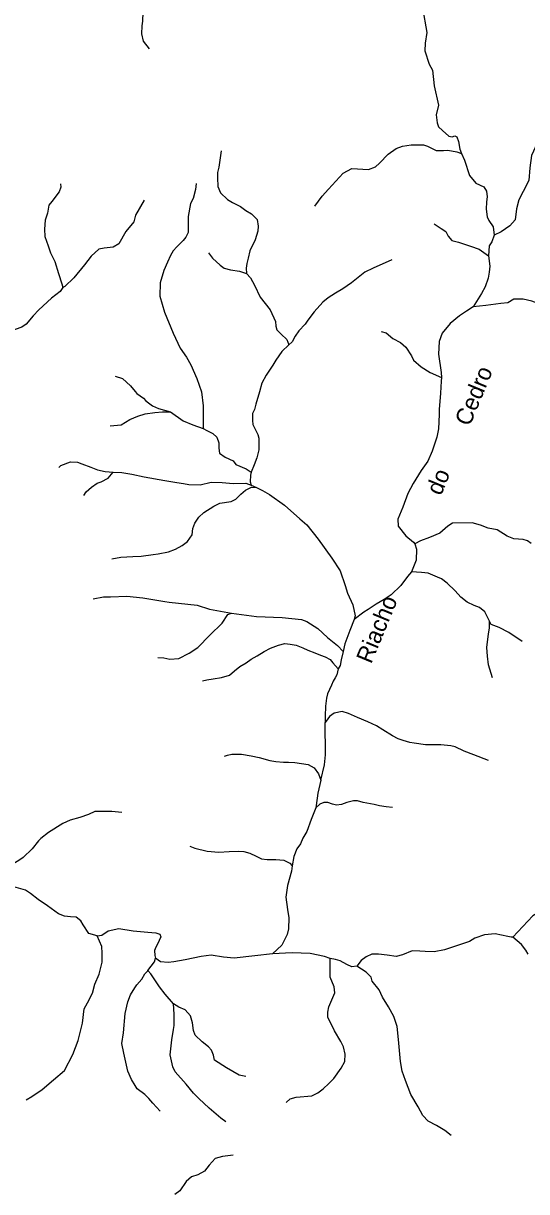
# Model space of a CAD drawing. Extents: x 717.8 to 772.7, y 8672.2 to 8728.
# Drawn here: x 755.19 to 761.18, y 8700.84 to 8714.76 of the extents above; entities that cross this region are included whole.
import ezdxf
from ezdxf.enums import TextEntityAlignment as Align

# ---------------------------------------------------------------- set-up
doc = ezdxf.new("R2010")
doc.units = 0
doc.header["$LTSCALE"] = 0.08
doc.linetypes.add('LONG_DASHED', pattern=[7.5, 6, -1.5])
doc.layers.add('61', color=7, linetype='Continuous')
doc.layers.add('9', color=7, linetype='LONG_DASHED', lineweight=25)

msp = doc.modelspace()

# ---------------------------------------------------------------- linework, layer by layer
at = {"layer": '9'}
for points in [[(759.8819, 8715.4201), (759.893, 8715.3655), (759.8987, 8715.3039), (759.905, 8715.2034), (759.9117, 8715.0996), (759.938, 8714.9401), (759.99, 8714.6467), (759.9703, 8714.5208), (759.967, 8714.4305), (760.0174, 8714.2699), (760.0568, 8714.1993), (760.0794, 8714.0103), (760.1298, 8713.7807), (760.1022, 8713.6647), (760.1121, 8713.5723), (760.1309, 8713.5228), (760.1789, 8713.48), (760.2538, 8713.4108), (760.2908, 8713.4041), (760.3245, 8713.4166), (760.349, 8713.406), (760.3687, 8713.35), (760.3845, 8713.2586), (760.4042, 8713.206)], [(756.688, 8714.4531), (756.6164, 8714.5436), (756.595, 8714.6315), (756.5994, 8714.7258), (756.6082, 8714.7823), (756.6129, 8714.8878), (756.5833, 8714.9933), (756.5507, 8715.1278), (756.5244, 8715.1785)], [(761.3778, 8713.4159), (761.3027, 8713.3282), (761.2362, 8713.1828), (761.2154, 8713.0358), (761.2052, 8712.8849), (761.1372, 8712.7549), (761.0846, 8712.6559), (761.0598, 8712.546), (761.0413, 8712.4176), (760.9787, 8712.3465), (760.875, 8712.273), (760.7924, 8712.2328)], [(757.5414, 8713.2372), (757.5143, 8713.0432), (757.4983, 8712.9809), (757.4958, 8712.9172), (757.5015, 8712.8125), (757.5318, 8712.7367), (757.6156, 8712.6593), (757.6747, 8712.621), (757.772, 8712.5739), (757.8351, 8712.5268), (757.9021, 8712.4877), (757.9684, 8712.4199), (757.9827, 8712.3401), (757.978, 8712.2826), (757.9444, 8712.1773), (757.8831, 8712.0467), (757.8627, 8711.9583), (757.8463, 8711.8964), (757.8399, 8711.8405), (757.8438, 8711.7769)], [(758.6555, 8712.5782), (758.743, 8712.6976), (758.8189, 8712.7828), (758.9939, 8712.9718), (759.0955, 8713.0282), (759.2967, 8713.0175), (759.3795, 8713.0462), (759.4264, 8713.0925), (759.5298, 8713.1965), (759.6273, 8713.2647), (759.7017, 8713.2918), (759.8055, 8713.3089), (759.9511, 8713.3089), (759.9983, 8713.2918), (760.1024, 8713.2426), (760.1886, 8713.2425), (760.2392, 8713.2461), (760.3476, 8713.2267), (760.4042, 8713.206)], [(760.4042, 8713.206), (760.4384, 8713.126), (760.4994, 8712.9429), (760.5735, 8712.8528), (760.6701, 8712.8101), (760.7018, 8712.7582), (760.708, 8712.6891), (760.7011, 8712.6311), (760.697, 8712.5439), (760.7085, 8712.4526), (760.7289, 8712.4099), (760.7787, 8712.3344), (760.7924, 8712.2328)], [(755.6293, 8712.843), (755.6304, 8712.8043), (755.6103, 8712.7509), (755.523, 8712.6363), (755.4882, 8712.5899), (755.472, 8712.4947), (755.4461, 8712.4124), (755.4358, 8712.3029), (755.442, 8712.2192), (755.4808, 8712.1078), (755.508, 8712.0247), (755.5597, 8711.9216), (755.606, 8711.7753), (755.6432, 8711.6542), (755.6552, 8711.6119)], [(757.2436, 8712.8502), (757.2368, 8712.7754), (757.2088, 8712.6701), (757.1765, 8712.6111), (757.1466, 8712.4574), (757.1481, 8712.2653), (757.1209, 8712.211), (757.087, 8712.1701), (757.0122, 8712.0953), (756.9713, 8712.0463), (756.9374, 8711.9905), (756.9034, 8711.9117), (756.8597, 8711.8109), (756.8144, 8711.6637), (756.8128, 8711.5068), (756.8662, 8711.3175), (756.9681, 8711.0659), (757.0532, 8710.8863), (757.1268, 8710.7803), (757.1794, 8710.6881), (757.2505, 8710.5279), (757.3059, 8710.3676), (757.3263, 8710.2022), (757.3282, 8710.0733), (757.3269, 8709.9324)], [(756.6227, 8712.6508), (756.5218, 8712.4708), (756.5007, 8712.3934), (756.4053, 8712.2776), (756.3207, 8712.1299), (756.2534, 8712.0916), (756.1471, 8712.079), (756.086, 8712.0665), (755.9942, 8711.9822), (755.9133, 8711.881), (755.7848, 8711.727), (755.681, 8711.6204), (755.6552, 8711.6119)], [(760.0788, 8712.3685), (760.1615, 8712.3142), (760.2182, 8712.2786), (760.2445, 8712.2201), (760.2879, 8712.1697), (760.3682, 8712.1498), (760.4491, 8712.1221), (760.5115, 8712.102), (760.6131, 8712.0662), (760.7258, 8711.9874)], [(760.7924, 8712.2328), (760.7646, 8712.1554), (760.7315, 8712.1069), (760.7258, 8711.9874)], [(757.3918, 8712.0242), (757.439, 8711.9611), (757.5276, 8711.8748), (757.5763, 8711.842), (757.652, 8711.8223), (757.7584, 8711.8061), (757.8438, 8711.7769)], [(759.5725, 8711.9408), (759.3518, 8711.8398), (759.2515, 8711.7912), (759.1333, 8711.6988), (759.0925, 8711.6649), (758.9919, 8711.5954), (758.9012, 8711.5431), (758.8152, 8711.4869), (758.7503, 8711.4337), (758.6483, 8711.3218), (758.5739, 8711.2223), (758.54, 8711.1748), (758.4681, 8711.0933), (758.421, 8711.031), (758.385, 8710.9614), (758.3464, 8710.9254)], [(760.7258, 8711.9874), (760.7416, 8711.8649), (760.7344, 8711.7929), (760.7201, 8711.721), (760.684, 8711.6163), (760.6408, 8711.5371), (760.543, 8711.381)], [(762.1176, 8711.942), (762.0721, 8711.8933), (761.9419, 8711.7839), (761.8503, 8711.7304), (761.7714, 8711.673), (761.716, 8711.6285), (761.6252, 8711.5012), (761.5752, 8711.4583), (761.4362, 8711.4109), (761.3499, 8711.4089), (761.2412, 8711.4458), (761.138, 8711.4701), (761.0273, 8711.4701), (760.9548, 8711.4257), (760.8724, 8711.4197), (760.6939, 8711.3949), (760.543, 8711.381)], [(757.8438, 8711.7769), (757.8441, 8711.7768), (757.89, 8711.727), (757.9367, 8711.639), (758.0038, 8711.4936), (758.1244, 8711.3442), (758.187, 8711.2059), (758.1926, 8711.1508), (758.2046, 8711.1053), (758.2565, 8711.0533), (758.3243, 8710.9894), (758.3464, 8710.9254)], [(755.6552, 8711.6119), (755.6221, 8711.5619), (755.5189, 8711.4836), (755.3709, 8711.3446), (755.3022, 8711.2711), (755.2183, 8711.1751), (755.1673, 8711.1394), (755.0889, 8711.1101), (755.0244, 8711.0778), (754.9101, 8710.9804), (754.867, 8710.9604), (754.8061, 8710.9556), (754.7273, 8710.9308), (754.6209, 8710.89), (754.5797, 8710.8904)], [(760.543, 8711.381), (760.4613, 8711.3288), (760.3782, 8711.2712), (760.2689, 8711.1816), (760.174, 8711.0669), (760.138, 8710.9656), (760.1314, 8710.8154), (760.1624, 8710.5973), (760.1636, 8710.5372)], [(759.4448, 8711.0874), (759.5045, 8711.0686), (759.5845, 8711.0044), (759.678, 8710.9538), (759.7397, 8710.9014), (759.8087, 8710.7961), (759.8311, 8710.7457), (759.9248, 8710.6643), (760.0317, 8710.5962), (760.1636, 8710.5372)], [(758.3464, 8710.9254), (758.2638, 8710.8494), (758.1923, 8710.7465), (758.1567, 8710.6859), (758.0775, 8710.5678), (758.0267, 8710.4725), (757.9993, 8710.3669), (757.954, 8710.22), (757.9384, 8710.1561), (757.916, 8710.1106), (757.9135, 8710.0266), (757.9198, 8709.9779), (757.9765, 8709.8604), (757.9893, 8709.8173), (757.9885, 8709.6759), (757.9658, 8709.581), (757.9325, 8709.4966), (757.8987, 8709.4094)], [(756.2774, 8710.5553), (756.368, 8710.5253), (756.4125, 8710.4817), (756.4634, 8710.4404), (756.5167, 8710.3726), (756.5389, 8710.3473), (756.6159, 8710.2936), (756.6456, 8710.2595), (756.7253, 8710.2011), (756.7942, 8710.1678), (756.9397, 8710.1273)], [(760.1636, 8710.5372), (760.16, 8710.4944), (760.1529, 8710.3505), (760.1387, 8710.1561), (760.1388, 8710.0986), (760.1313, 8709.9281), (760.1097, 8709.8274), (760.0524, 8709.662), (760.0023, 8709.5398), (759.9238, 8709.4318), (759.8293, 8709.2759), (759.7642, 8709.1558), (759.7055, 8708.9923), (759.6436, 8708.8498), (759.6478, 8708.7664), (759.7385, 8708.6528), (759.8308, 8708.5761), (759.8466, 8708.5562)], [(756.2212, 8709.9619), (756.3514, 8709.9744), (756.4554, 8710.0398), (756.5469, 8710.0773), (756.6379, 8710.1064), (756.7495, 8710.1231), (756.8445, 8710.1299), (756.9397, 8710.1273)], [(756.9397, 8710.1273), (757.0883, 8710.023), (757.2048, 8709.9761), (757.3269, 8709.9324)], [(757.3269, 8709.9324), (757.3705, 8709.9052), (757.4428, 8709.8716), (757.4878, 8709.8284), (757.5117, 8709.7605), (757.5121, 8709.6958), (757.521, 8709.6376), (757.59, 8709.588), (757.6844, 8709.5446), (757.7143, 8709.5033), (757.8404, 8709.4507), (757.8987, 8709.4094)], [(755.6082, 8709.4666), (755.6331, 8709.4899), (755.7486, 8709.5329), (755.8298, 8709.53), (755.8805, 8709.5102), (755.99, 8709.4683), (756.0676, 8709.4396), (756.1617, 8709.4195), (756.2551, 8709.4123)], [(755.9063, 8709.1309), (755.9342, 8709.1762), (755.997, 8709.2312), (756.0659, 8709.2809), (756.1126, 8709.2966), (756.1957, 8709.3375), (756.2551, 8709.4123)], [(756.2551, 8709.4123), (756.357, 8709.4056), (756.4793, 8709.3853), (756.6254, 8709.3542), (756.8704, 8709.3123), (757.0116, 8709.2879), (757.0918, 8709.2748), (757.1563, 8709.2654), (757.2905, 8709.261), (757.4204, 8709.2924), (757.5546, 8709.2881), (757.6845, 8709.275), (757.8349, 8709.2777), (757.8994, 8709.2567), (757.9606, 8709.2295)], [(757.8987, 8709.4094), (757.8898, 8709.3747), (757.8884, 8709.2968), (757.8994, 8709.2567)], [(756.241, 8708.378), (756.3466, 8708.399), (756.4878, 8708.4077), (756.588, 8708.4112), (756.7327, 8708.4286), (756.7928, 8708.4374), (756.914, 8708.4618), (756.9977, 8708.4949), (757.0781, 8708.5362), (757.1392, 8708.5837), (757.1955, 8708.6655), (757.2025, 8708.7414), (757.2269, 8708.8016), (757.274, 8708.8748), (757.3358, 8708.9304), (757.4553, 8709.0039), (757.525, 8709.0405), (757.6601, 8709.0623), (757.715, 8709.0884), (757.7773, 8709.1479), (757.8315, 8709.1955), (757.9023, 8709.2305), (757.9606, 8709.2295)], [(757.9606, 8709.2295), (758.034, 8709.1913), (758.1168, 8709.1451), (758.2938, 8709.0186), (758.4774, 8708.8554), (758.5596, 8708.7832), (758.6951, 8708.6107), (758.8582, 8708.3863), (758.957, 8708.2343), (759.0163, 8708.0625), (759.0476, 8707.9692), (759.109, 8707.8299), (759.1384, 8707.6999), (759.1252, 8707.6547)], [(761.2315, 8708.5608), (761.1902, 8708.5937), (761.1387, 8708.6094), (761.0247, 8708.6164), (760.9473, 8708.6474), (760.8273, 8708.7249), (760.7197, 8708.7443), (760.6293, 8708.7801), (760.53, 8708.8055), (760.2945, 8708.8016), (760.2395, 8708.7675), (760.1458, 8708.6838), (760.0216, 8708.6306), (759.9168, 8708.5917), (759.8466, 8708.5562)], [(759.8466, 8708.5562), (759.8694, 8708.4915), (759.8616, 8708.3606), (759.8084, 8708.2239)], [(759.8084, 8708.2239), (759.7623, 8708.1674), (759.679, 8708.0605), (759.5643, 8707.9503), (759.4833, 8707.8944), (759.3866, 8707.838), (759.2937, 8707.7747), (759.2411, 8707.7419), (759.1252, 8707.6547)], [(760.7371, 8707.6344), (760.6795, 8707.7462), (760.6183, 8707.7972), (760.5533, 8707.8236), (760.4717, 8707.8606), (760.3944, 8707.9208), (760.3267, 8707.996), (760.2335, 8708.0902), (760.1643, 8708.1385), (760.1191, 8708.1613), (760.0048, 8708.2078), (759.9264, 8708.2164), (759.8084, 8708.2239)], [(756.0173, 8707.9008), (756.1388, 8707.9251), (756.2221, 8707.927), (756.419, 8707.9341), (756.6075, 8707.9152), (756.8694, 8707.8693), (756.9206, 8707.8603), (757.2546, 8707.826), (757.4041, 8707.7785), (757.6647, 8707.73)], [(756.7867, 8707.2048), (756.8587, 8707.2003), (756.928, 8707.1823), (757.0358, 8707.1895), (757.1621, 8707.2544), (757.2641, 8707.3223), (757.4065, 8707.4703), (757.5514, 8707.6126), (757.6225, 8707.7152), (757.6647, 8707.73)], [(757.6647, 8707.73), (757.9636, 8707.69), (758.2695, 8707.6792), (758.4998, 8707.6567), (758.561, 8707.6333), (758.6915, 8707.5478), (758.8085, 8707.4424), (758.9274, 8707.346), (758.9938, 8707.2753)], [(759.1252, 8707.6547), (759.0751, 8707.5232), (759.0138, 8707.3679), (758.9938, 8707.2753)], [(760.7731, 8706.9606), (760.7237, 8707.1174), (760.713, 8707.2205), (760.7051, 8707.3212), (760.7233, 8707.4834), (760.7357, 8707.5538), (760.7371, 8707.6344)], [(761.1266, 8707.3938), (760.9671, 8707.5022), (760.8511, 8707.5608), (760.7582, 8707.5973), (760.7371, 8707.6344)], [(757.3176, 8706.9258), (757.3698, 8706.939), (757.4456, 8706.9495), (757.5459, 8706.9669), (757.64, 8706.994), (757.7002, 8707.0454), (757.7621, 8707.0943), (757.8383, 8707.1389), (757.8997, 8707.1815), (757.9693, 8707.2224), (758.0526, 8707.2749), (758.1289, 8707.3131), (758.224, 8707.3488), (758.3003, 8707.3702), (758.3622, 8707.3631), (758.436, 8707.3487), (758.5122, 8707.32), (758.5741, 8707.289), (758.6551, 8707.2579), (758.7246, 8707.2293), (758.7812, 8707.2125), (758.8386, 8707.1793), (758.8716, 8707.1394), (758.936, 8707.0668)], [(758.9938, 8707.2753), (758.9693, 8707.1742), (758.9566, 8707.1091), (758.936, 8707.0668)], [(758.936, 8707.0668), (758.918, 8706.9961), (758.8978, 8706.9595), (758.8764, 8706.9213), (758.8542, 8706.8718), (758.8311, 8706.8212), (758.8083, 8706.77), (758.7948, 8706.7169), (758.7858, 8706.6565), (758.7827, 8706.6218), (758.7786, 8706.5039), (758.7794, 8706.4286)], [(760.7258, 8705.9778), (760.5509, 8706.0458), (760.4343, 8706.0876), (760.3262, 8706.1377), (760.275, 8706.1525), (760.159, 8706.1624), (760.0555, 8706.1621), (759.9744, 8706.1614), (759.8406, 8706.1813), (759.7874, 8706.1921), (759.7072, 8706.2136), (759.6488, 8706.2334), (759.583, 8706.2704), (759.4679, 8706.3424), (759.3914, 8706.3901), (759.2897, 8706.4387), (759.1655, 8706.4891), (759.0565, 8706.5359), (758.9807, 8706.5592), (758.8883, 8706.5409), (758.8333, 8706.4993), (758.8118, 8706.4731), (758.7794, 8706.4286)], [(758.7295, 8705.742), (758.7703, 8705.9244), (758.7821, 8706.0434), (758.7794, 8706.4286)], [(757.5809, 8706.0273), (757.6151, 8706.0417), (757.6691, 8706.0516), (757.7851, 8706.0507), (757.8987, 8706.0328), (757.993, 8706.0102), (758.1199, 8705.9748), (758.1939, 8705.9648), (758.2836, 8705.9561), (758.3435, 8705.9553), (758.4203, 8705.9542), (758.5787, 8705.9274), (758.6485, 8705.8897), (758.7005, 8705.8156), (758.7295, 8705.742)], [(758.7295, 8705.742), (758.6944, 8705.5878), (758.683, 8705.5263), (758.6701, 8705.4135)], [(758.6701, 8705.4135), (758.6137, 8705.273), (758.5626, 8705.1303), (758.5158, 8705.0526), (758.4855, 8704.9835), (758.4421, 8704.9232), (758.4065, 8704.8312), (758.3873, 8704.7222)], [(759.5801, 8705.4152), (759.5054, 8705.4242), (759.4271, 8705.4348), (759.3641, 8705.4522), (759.2317, 8705.4746), (759.1637, 8705.4955), (759.1162, 8705.4951), (759.0383, 8705.4765), (758.9727, 8705.4504), (758.9133, 8705.4432), (758.868, 8705.4559), (758.8117, 8705.4772), (758.7623, 8705.478), (758.7171, 8705.455), (758.6701, 8705.4135)], [(756.3571, 8705.3558), (756.2387, 8705.367), (756.0376, 8705.3681), (755.9629, 8705.3346), (755.8575, 8705.2961), (755.7426, 8705.2642), (755.6546, 8705.2247), (755.4855, 8705.1196), (755.3954, 8705.0489), (755.3669, 8705.0189), (755.289, 8704.9262), (755.1819, 8704.8229), (755.1314, 8704.7856), (755.0311, 8704.7241), (754.9598, 8704.6808), (754.9186, 8704.6458), (754.846, 8704.5731)], [(757.1666, 8704.9564), (757.2291, 8704.9313), (757.3748, 8704.8957), (757.5119, 8704.8827), (757.6354, 8704.8916), (757.7419, 8704.8956), (757.812, 8704.8916), (757.8807, 8704.8739), (757.9571, 8704.8383), (758.0213, 8704.806), (758.0907, 8704.7991), (758.1923, 8704.7964), (758.2873, 8704.7896), (758.3576, 8704.7544), (758.3873, 8704.7222)], [(758.3873, 8704.7222), (758.3776, 8704.6587), (758.3323, 8704.4893), (758.3133, 8704.3493), (758.3302, 8704.2001), (758.3453, 8704.1013), (758.3439, 8703.9729), (758.3282, 8703.9045), (758.2935, 8703.832), (758.2649, 8703.7761), (758.1521, 8703.6739)], [(756.0637, 8703.8868), (755.9642, 8703.9141), (755.8985, 8704.0199), (755.8696, 8704.0653), (755.8146, 8704.1106), (755.7471, 8704.1154), (755.6739, 8704.1203), (755.6045, 8704.1482), (755.4743, 8704.2437), (755.3634, 8704.3218), (755.2691, 8704.3939), (755.2091, 8704.4306), (755.0443, 8704.481), (755.0039, 8704.4964), (754.8883, 8704.5751), (754.846, 8704.5731)], [(762.2137, 8704.5766), (762.1827, 8704.5767), (762.0839, 8704.5251), (762.0033, 8704.5279), (761.9541, 8704.5495), (761.8948, 8704.5503), (761.8585, 8704.5483), (761.7993, 8704.5264), (761.7527, 8704.5354), (761.6721, 8704.4575), (761.5225, 8704.3557), (761.4016, 8704.2394), (761.3307, 8704.1735), (761.2512, 8704.1248), (761.0154, 8703.8709)], [(755.2188, 8701.935), (755.2867, 8701.9759), (755.4091, 8702.0577), (755.5449, 8702.1735), (755.674, 8702.2824), (755.776, 8702.4728), (755.8373, 8702.6428), (755.8917, 8702.8468), (755.9089, 8703.0199), (755.948, 8703.0881), (756.0083, 8703.2043), (756.0351, 8703.3127), (756.0889, 8703.4315), (756.123, 8703.5742), (756.123, 8703.6287), (756.123, 8703.683), (756.1221, 8703.7615), (756.0637, 8703.8868)], [(756.0637, 8703.8868), (756.1208, 8703.8968), (756.1961, 8703.949), (756.3236, 8703.9746), (756.4952, 8703.9457), (756.6686, 8703.9332), (756.765, 8703.9236), (756.8123, 8703.9091), (756.8219, 8703.8744), (756.7814, 8703.787), (756.764, 8703.7529), (756.7486, 8703.7143), (756.7506, 8703.6545), (756.7598, 8703.6209)], [(761.0154, 8703.8709), (760.9939, 8703.8741), (760.9563, 8703.882), (760.8061, 8703.9126), (760.6777, 8703.9016), (760.562, 8703.8585), (760.4969, 8703.8213), (760.3686, 8703.7749), (760.2022, 8703.7208), (760.0763, 8703.6955), (759.9725, 8703.7001), (759.9081, 8703.7039), (759.8174, 8703.7087), (759.7014, 8703.6625), (759.6255, 8703.6428), (759.5185, 8703.6595), (759.4152, 8703.6716), (759.3338, 8703.6686), (759.2685, 8703.6368), (759.2071, 8703.5946), (759.1553, 8703.5248)], [(761.1962, 8703.6715), (761.169, 8703.7168), (761.1182, 8703.7866), (761.0154, 8703.8709)], [(756.6673, 8703.4741), (756.7486, 8703.5764), (756.7598, 8703.6209)], [(758.1521, 8703.6739), (757.941, 8703.6497), (757.6971, 8703.6217), (757.5699, 8703.6333), (757.4225, 8703.6584), (757.3029, 8703.6422), (757.1111, 8703.6024), (756.9783, 8703.5784), (756.9096, 8703.5687), (756.8171, 8703.5793), (756.7891, 8703.5986), (756.7598, 8703.6209)], [(758.8377, 8703.6161), (758.7726, 8703.6414), (758.6011, 8703.679), (758.3871, 8703.6865), (758.1521, 8703.6739)], [(758.314, 8701.9022), (758.3642, 8701.9479), (758.434, 8701.9667), (758.6214, 8701.9824), (758.693, 8702.0182), (758.7542, 8702.0658), (758.8234, 8702.1295), (758.8842, 8702.1886), (758.9708, 8702.3125), (759.0151, 8702.3897), (759.0196, 8702.479), (758.9993, 8702.5668), (758.9656, 8702.6305), (758.8928, 8702.7573), (758.8651, 8702.8173), (758.8119, 8702.9169), (758.8109, 8702.9779), (758.8252, 8703.0417), (758.8934, 8703.2082), (758.8874, 8703.2794), (758.838, 8703.3972), (758.8381, 8703.4973), (758.8403, 8703.5775), (758.8377, 8703.6161)], [(759.1553, 8703.5248), (759.0993, 8703.5176), (759.039, 8703.5485), (758.9572, 8703.5884), (758.9044, 8703.6043), (758.8377, 8703.6161)], [(756.814, 8701.8014), (756.7261, 8701.8936), (756.6783, 8701.9501), (756.6322, 8701.9997), (756.54, 8702.0666), (756.5162, 8702.1065), (756.4722, 8702.1754), (756.4314, 8702.2745), (756.3816, 8702.4891), (756.3582, 8702.6037), (756.3774, 8702.7329), (756.3968, 8702.9636), (756.4307, 8703.1032), (756.4629, 8703.1847), (756.5134, 8703.2686), (756.5368, 8703.3041), (756.5949, 8703.3703), (756.6304, 8703.4365), (756.6663, 8703.4727), (756.6673, 8703.4741)], [(756.9738, 8703.0785), (756.8748, 8703.1952), (756.8087, 8703.2807), (756.7353, 8703.3889), (756.7046, 8703.4356), (756.6673, 8703.4741)], [(760.2804, 8701.5117), (760.2045, 8701.5687), (760.107, 8701.6291), (760.0063, 8701.6794), (759.941, 8701.75), (759.8872, 8701.8495), (759.7984, 8701.999), (759.7354, 8702.1669), (759.6975, 8702.2762), (759.6762, 8702.3893), (759.6522, 8702.655), (759.6372, 8702.8093), (759.5971, 8702.9275), (759.5349, 8703.0422), (759.4643, 8703.1568), (759.4218, 8703.2441), (759.3414, 8703.3474), (759.3262, 8703.3961), (759.2689, 8703.4564), (759.1553, 8703.5248)], [(757.598, 8701.6721), (757.5357, 8701.7163), (757.3986, 8701.8349), (757.2751, 8701.9519), (757.2114, 8702.0132), (757.1228, 8702.1204), (756.9938, 8702.2698), (756.9649, 8702.3278), (756.9335, 8702.4697), (756.9532, 8702.6504), (756.9737, 8702.7727), (756.9827, 8702.8207), (756.9806, 8702.9562), (756.9738, 8703.0785)], [(757.8354, 8702.2108), (757.7547, 8702.2294), (757.6051, 8702.3175), (757.463, 8702.4052), (757.449, 8702.4671), (757.4275, 8702.5246), (757.3896, 8702.5674), (757.3145, 8702.6239), (757.2331, 8702.7037), (757.2129, 8702.7618), (757.1992, 8702.8514), (757.1765, 8702.9337), (757.1136, 8703.0055), (757.0362, 8703.0386), (756.9738, 8703.0785)], [(757.6855, 8701.2766), (757.5554, 8701.2612), (757.4702, 8701.2347), (757.3999, 8701.1563), (757.3424, 8701.0832), (757.2622, 8701.0406), (757.1888, 8701.0159), (757.1242, 8700.9635), (757.05, 8700.8522), (756.9906, 8700.8076)]]:
    msp.add_lwpolyline(points, dxfattribs=at)

# ---------------------------------------------------------------- texts
at = {"layer": '61'}
msp.add_text('Riacho                  do        Cedro', height=0.2, rotation=67.464, dxfattribs=at).set_placement((760.0534, 8708.8689), align=Align.CENTER)

doc.saveas('drawing.dxf')
